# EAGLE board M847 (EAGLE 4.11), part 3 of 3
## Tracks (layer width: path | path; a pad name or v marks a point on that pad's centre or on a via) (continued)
N$122
  Bottom 0.254: E37.6 5.71,92.08 5.71,87.63 18.41,87.63 19.68,88.9 20.95,88.9 22.23,87.63 C4.1
N$123
  Top 0.254: C5.1 20.32,88.27 17.78,90.81 17.78,99.06 E37.14
N$124
  Top 0.254: C5.2 R37.2 20.32,99.06 E37.15
N$125
  Top 0.254: E37.5 5.71,98.43 5.71,104.78 E37.1
N$126  (via drill 0.61)
  Top 0.254: E19.5 128.27,104.14 125.73,106.68 125.73,122.56 124.46,123.83 R38.1 | v152.4,102.87 156.21,106.68 E16.12
  Bottom 0.254: E16.12 E13.1 | v152.4,102.87 132.08,102.87 130.81,104.14 E19.5
N$127  (via drill 0.61)
  Top 0.254: R38.2 C7.1 | v159.38,130.18 159.38,106.05 E16.11
  Bottom 0.254: E16.11 E13.2 | v159.38,130.18 154.94,134.62 C7.1
N$128
  Top 0.254: E16.2 E16.13
N$129
  Top 0.254: E16.3 147.96,104.78 147.96,103.51 E16.5
  Bottom 0.254: E16.5 E16.10
N$130
  Bottom 0.254: E16.6 151.13,99.06 152.4,100.33 162.56,100.33 163.83,101.6 E13.3
N$131
  Bottom 0.254: E16.1 151.13,111.76 154.94,115.57 158.75,115.57 161.93,118.75 254.63,118.75 256.54,116.84 256.54,97.79 257.81,97.79 259.08,96.52 259.08,74.3 252.09,74.3 E2.12
N$132
  Top 0.254: E5.9 233.04,66.68 233.04,67.95 E5.10
  Bottom 0.254: E2.13 250.19,76.2 248.92,74.93 242.57,74.93 241.94,74.3 241.94,73.03 242.57,72.39 245.11,72.39 245.75,71.76 245.75,69.85 236.22,69.85 234.95,68.58 E5.10
N$133  (via drill 0.61)
  Top 0.254: T2.2 v146.05,104.14 146.05,88.27 v145.41,87.63
  Bottom 0.254: E16.4 v146.05,104.14 | v145.41,87.63 181.61,87.63 186.69,82.55 236.85,82.55 238.12,81.28 R39.1
N$134
  Top 0.254: E5.8 231.78,65.41 231.78,74.3 E5.13
N$135  (via drill 0.61)
  Top 0.254: v165.74,60.96 165.74,61.6 E12.10 | v132.08,59.06 132.08,63.5 E18.6
  Bottom 0.254: E18.6 133.35,66.04 132.08,67.31 109.86,67.31 109.86,65.41 E22.8 110.49,63.5 109.22,62.23 49.53,62.23 46.99,64.77 17.78,64.77 16.51,66.04 E36.9 | v165.74,60.96 163.83,59.06 v132.08,59.06
N$136  (via drill 0.61)
  Top 0.254: v184.78,71.12 184.78,99.7 E10.3
  Bottom 0.254: v184.78,71.12 186.06,69.85 231.14,69.85 232.41,71.12 E5.11
N$137  (via drill 0.61)
  Top 0.254: v26.04,62.23 v26.04,71.12
  Bottom 0.254: v26.04,62.23 17.78,62.23 16.51,63.5 E36.8 | v26.04,71.12 E33.11
N$138  (via drill 0.61)
  Top 0.254: v21.59,93.98 21.59,92.08 27.3,86.36 27.3,58.42 32.38,58.42 33.66,59.69 33.66,65.41 E33.10
  Bottom 0.254: v21.59,93.98 E37.11
N$139  (via drill 0.61)
  Top 0.254: 130.18,76.2 132.72,76.2 132.72,73.03 E18.4 | E20.13 130.18,76.2 | v107.31,78.74 107.31,102.24 E23.4 | v163.19,81.28 163.19,80.65 E12.1 | 130.18,76.2 v130.18,81.28
  Bottom 0.254: v107.31,78.74 108.58,77.47 124.46,77.47 125.73,76.2 E20.13 | v130.18,81.28 v163.19,81.28
N$140  (via drill 0.61)
  Top 0.254: E20.11 126.36,71.76 126.36,73.03 E20.12 | v71.12,72.39 71.12,76.2 E27.14
  Bottom 0.254: v71.12,72.39 123.83,72.39 125.09,73.66 E20.12
N$141  (via drill 0.61)
  Top 0.254: v131.44,71.76 131.44,74.93 125.73,74.93 125.09,75.57 125.09,76.84 E20.14
  Bottom 0.254: v131.44,71.76 132.08,72.39 154.94,72.39 156.21,71.12 E15.11
N$142
  Top 0.254: D385.C 114.3,153.67 111.76,156.21 D386.A
N$143
  Top 0.254: E2.5 243.21,69.22 243.21,70.49 E2.4 | 170.18,92.71 170.81,92.71 170.81,97.16 E13.11 | 170.18,92.71 163.83,92.71 161.93,90.81 161.93,70.49 E15.9 | 170.18,92.71 170.18,73.66 E12.11
  Bottom 0.254: E13.11 R53.1 | E2.4 242.57,71.12 241.3,72.39 175.26,72.39 173.99,71.12 E12.11
N$144
  Top 0.254: E22.11 111.12,71.76 111.12,73.03 E22.12 113.67,75.57 113.67,82.55 111.12,85.09 111.12,97.16 E23.6
N$145  (via drill 0.61)
  Top 0.254: v113.67,102.87 114.94,101.6 114.94,78.11 E20.3
  Bottom 0.254: E20.3 120.65,73.66 121.92,74.93 162.56,74.93 163.83,73.66 E12.3 | v113.67,102.87 90.17,102.87 89.53,102.24 88.27,102.24 87.63,101.6 E24.3
N$147
  Bottom 0.254: E15.8 158.75,63.5 160.02,64.77 170.18,64.77 171.45,66.04 E12.9 173.99,66.04 175.26,67.31 223.52,67.31 224.79,68.58 E5.5
N$148  (via drill 0.61)
  Top 0.254: v214.63,64.14 223.52,73.03 223.52,76.2 E5.1
  Bottom 0.254: v214.63,64.14 174.62,64.14 173.99,63.5 E12.8
N$149  (via drill 0.61)
  Top 0.254: v121.92,71.12 121.92,73.66 E20.2
  Bottom 0.254: v121.92,71.12 123.19,69.85 130.81,69.85 133.35,67.31 147.32,67.31 148.59,68.58 E15.5
N$151  (via drill 0.61)
  Top 0.254: v121.92,59.06 121.92,68.58 E20.4
  Bottom 0.254: v121.92,59.06 123.19,57.79 231.78,57.79 241.3,67.31 245.11,67.31 246.38,68.58 246.38,73.03 244.47,73.03 E2.3
N$152  (via drill 0.61)
  Top 0.254: E15.10 161.29,72.39 161.29,97.79 163.83,100.33 170.81,100.33 170.81,102.24 171.45,102.87 180.34,102.87 180.34,99.06 E10.5 | v113.03,96.52 111.76,97.79 111.76,104.14 E23.3
  Bottom 0.254: v113.03,96.52 114.3,95.25 161.29,95.25 163.83,97.79 180.34,97.79 181.61,96.52 E10.5
POWER_OK\  (via drill 0.61)
  Top 0.254: E27.9 67.94,66.68 67.94,67.95 E27.10 | v74.93,118.75 v74.93,68.58 | v146.69,19.05 150.5,22.86 v150.5,45.72
  Bottom 0.254: 146.69,123.19 149.22,120.65 259.08,120.65 261.62,118.11 261.62,71.76 252.09,71.76 E2.11 245.11,64.77 242.57,64.77 232.41,54.61 159.38,54.61 v150.5,45.72 | 146.69,123.19 145.41,124.46 T2.3 | v74.93,118.75 79.38,123.19 146.69,123.19 | v74.93,68.58 E27.10 | v146.69,19.05 143.51,19.05 138.43,13.97 U$2.BV2
PULSE_LA  (via drill 0.61)
  Top 0.254: v19.05,15.24 19.05,47.63 12.7,53.98 12.7,105.41 11.43,106.68 11.43,212.73 95.89,212.73 99.69,208.92 99.69,195.58 T1.1
  Bottom 0.254: v19.05,15.24 17.78,13.97 U$2.DR2
RUN\  (via drill 0.61)
  Top 0.254: E16.9 156.84,98.43 156.84,97.16 E16.8 159.38,94.62 159.38,73.03 v160.02,72.39 | v152.4,17.78 156.21,21.59 156.21,26.67 161.29,31.75 168.28,31.75 168.28,36.2 168.91,36.83 172.72,36.83 172.72,41.91 194.31,63.5 194.31,66.68 195.58,67.95 v195.58,74.93
  Bottom 0.254: v160.02,72.39 173.99,72.39 174.62,73.03 185.42,73.03 187.32,74.93 v195.58,74.93 231.14,74.93 232.41,73.66 E5.12 | v152.4,17.78 145.41,17.78 141.6,13.97 U$2.BU2
SET_GO
  Top 0.254: E18.11 144.15,73.03 144.15,97.16 E19.12
SHIFT_CLOCK
  Top 0.254: E25.8 E24.4
  Bottom 0.254: E6.8 234.95,91.44 233.68,92.71 208.28,92.71 207.01,91.44 E9.8 204.47,91.44 203.2,92.71 81.92,92.71 80.64,91.44 E25.8 77.47,91.44 75.56,89.54 51.44,89.54 49.53,91.44 E31.8
START_ADD\  (via drill 0.61)
  Top 0.254: v231.14,30.48 231.14,68.58 E5.3 | v123.83,29.21 123.83,13.97 U$2.CB1
  Bottom 0.254: 160.02,29.21 v123.83,29.21 63.5,29.21 62.23,30.48 E26.7 | 160.02,29.21 161.29,30.48 E11.7 | 160.02,29.21 210.82,29.21 212.09,30.48 E7.7 217.17,30.48 218.44,29.21 229.87,29.21 v231.14,30.48
STOP\  (via drill 0.61)
  Top 0.254: v108.58,54.61 108.58,65.41 E22.10 | v62.23,49.53 51.44,38.74 v51.44,19.05
  Bottom 0.254: v108.58,54.61 103.5,49.53 v62.23,49.53 | v51.44,19.05 48.9,16.51 17.14,16.51 14.61,13.97 U$2.DS2
SW  (via drill 0.61)
  Top 0.254: v36.2,18.42 50.8,33.02 R32.2
  Bottom 0.254: v36.2,18.42 35.56,17.78 8.89,17.78 5.08,13.97 U$2.DV2
SYSTEM_CLEAR\  (via drill 0.61)
  Top 0.254: E31.9 43.18,88.9 43.18,78.74 E30.13 | v158.12,93.98 154.31,90.17 154.31,81.92 151.13,78.74 E15.1
  Bottom 0.254: E6.9 234.31,93.98 233.04,95.25 208.28,95.25 207.01,93.98 E9.9 204.47,93.98 203.2,95.25 162.56,95.25 161.29,93.98 v158.12,93.98 | 41.27,76.84 41.91,76.2 E30.13 | 41.27,76.84 39.37,78.74 E30.1 | E25.9 77.47,93.98 76.2,95.25 50.8,95.25 49.53,93.98 E31.9 | 41.27,76.84 44.45,80.01 147.32,80.01 148.59,78.74 E15.1
TP4  (via drill 0.61)
  Top 0.254: E20.7 118.75,64.14 118.75,65.41 E20.6 118.75,66.68 118.75,67.95 E20.5 | v32.38,59.69 32.38,64.14 E33.9 | v104.78,15.88 102.23,18.42 v102.23,60.33
  Bottom 0.254: v32.38,59.69 33.02,60.33 v102.23,60.33 103.5,61.6 116.2,61.6 118.11,63.5 E20.7 | v104.78,15.88 104.78,13.97 U$2.CJ2
TS1\  (via drill 0.61)
  Top 0.254: E27.4 60.33,70.49 60.33,69.22 E27.5 62.23,68.58 66.67,64.14 v66.67,54.61 | v95.89,50.8 99.69,46.99 v99.69,15.24
  Bottom 0.254: v66.67,54.61 70.48,50.8 v95.89,50.8 | v99.69,15.24 100.33,14.61 100.97,14.61 101.6,13.97 U$2.CK2
TS3\  (via drill 0.61)
  Top 0.254: E20.10 126.36,67.95 126.36,66.68 E20.9 128.91,64.14 v128.91,18.42
  Bottom 0.254: v128.91,18.42 127.64,17.15 100.33,17.15 97.16,13.97 U$2.CM2
VCC  (via drill 0.61)
  Top 0.635: E7.16 219.71,46.99 C13.1 | E11.16 168.91,46.99 C23.1 | R12.2 R13.2 R14.2 | R15.2 R4.2 R5.2 R6.2 R7.2 | C18.1 250.19,26.04 250.82,26.67 250.82,29.85 E1.8 249.56,32.39 249.56,50.8 C17.1 250.19,51.44 250.82,52.07 250.82,62.87 E2.8 249.56,65.41 249.56,82.55 C16.1 | E4.14 234.95,46.99 C14.1 234.95,51.44 238.76,55.25 R39.2 238.76,71.76 235.59,74.93 235.59,76.84 E5.14 233.04,79.38 233.04,82.55 232.41,83.19 C12.1 | C24.1 171.45,83.19 172.09,82.55 172.09,79.38 E12.14 | C27.1 156.21,83.19 156.84,82.55 156.84,79.38 E15.14 153.67,74.93 C28.1 153.67,46.99 E14.14 | C30.1 140.97,83.19 141.6,82.55 141.6,79.38 E18.14 | C39.1 110.49,83.19 111.12,82.55 111.12,79.38 E22.14 | E20.8 123.19,67.31 123.19,80.65 125.73,83.19 C35.1 125.73,84.46 118.75,91.44 118.75,109.86 E23.14 115.57,113.03 C32.1 | v138.43,26.04 138.43,29.21 E17.8 | R23.2 R22.2 R21.2 R20.2 R3.2 82.55,45.09 80.64,43.18 80.64,36.83 80.01,36.2 R2.2 | C36.1 113.03,46.99 E21.14 116.2,43.82 116.2,28.58 C8.+ 122.56,22.23 v122.56,15.88 | E35.8 13.34,32.39 13.34,50.8 C42.1 | E32.14 29.21,46.99 C46.1 | E29.14 44.45,46.99 C44.1 44.45,51.44 49.53,56.52 49.53,69.85 52.07,72.39 | E26.16 67.94,46.36 67.94,62.87 E27.8 66.67,65.41 66.67,72.39 | 66.67,72.39 66.67,82.55 67.31,83.19 C47.1 67.31,84.46 64.77,87 64.77,87.63 61.59,90.81 61.59,111.76 C48.1 62.23,107.95 E28.14 | C33.1 44.45,83.19 45.09,82.55 45.09,79.38 E30.14 | C38.1 13.97,83.19 14.61,82.55 14.61,79.38 E36.14 | C45.1 29.21,83.19 29.84,82.55 29.84,79.38 E33.14 | 66.67,72.39 52.07,72.39 | 52.07,72.39 C2.+ | D385.A R30.2 114.3,184.79 111.76,187.33 R28.2 | R40.1 R46.1 147.32,192.41 148.59,191.14 148.59,177.8
  Top 0.635: 148.59,177.8 R47.1 147.32,177.17 148.59,175.9 148.59,162.56 | 148.59,177.8 R41.1 | 148.59,162.56 R48.1 147.32,161.93 148.59,160.66 148.59,147.32 | 148.59,162.56 R42.1 | 148.59,147.32 R49.1 | 148.59,147.32 R43.1 149.86,146.69 152.4,144.15 R51.1 | R51.1 R45.1 | R44.1 149.86,132.72 152.4,135.26 R51.1 | E25.14 77.47,107.95 C43.1 | E24.14 92.71,107.95 C40.1 | R37.1 E37.16 14.61,107.32 14.61,110.49 13.97,111.13 C34.1 | E34.14 34.29,107.95 C41.1 | E31.14 46.99,107.95 C37.1 | E3.14 250.19,107.95 C15.1 | E6.14 234.95,107.95 C19.1 | E8.14 219.71,107.95 C20.1 | E10.14 189.23,107.95 C22.1 | E9.14 204.47,107.95 C21.1 | E13.14 171.45,107.95 C25.1 | C26.1 156.21,116.21 156.84,115.57 156.84,112.4 E16.14 | E19.16 135.89,115.57 C31.1 R31.1 142.24,126.37 147.32,131.45 R50.1
  Bottom 0.635: R14.2 R15.2 | R12.2 E11.16 168.91,45.72 167.64,46.99 157.48,46.99 156.21,45.72 E14.14 | R7.2 207.65,45.72 208.91,46.99 218.44,46.99 219.71,45.72 E7.16 222.25,45.72 223.52,44.45 233.68,44.45 234.95,45.72 E4.14 | C18.1 256.54,25.4 C11.+ 259.71,22.23 259.71,13.97 260.35,13.97 U$2.AA2 | C16.1 249.56,82.55 248.28,83.82 C12.1 | 123.83,85.09 125.09,83.82 C35.1 | 123.83,85.09 112.39,85.09 111.12,83.82 C39.1 | 139.06,85.09 140.34,83.82 C30.1 | 139.06,85.09 123.83,85.09 | 154.31,85.09 155.57,83.82 C27.1 | 154.31,85.09 139.06,85.09 | 154.31,85.09 169.54,85.09 170.81,83.82 C24.1 | U$2.BA2 190.5,13.97 189.23,15.24 187.96,15.24 C10.+ 177.8,25.4 137.79,25.4 | 137.79,25.4 135.89,23.5 122.56,23.5 C8.+ | 137.79,25.4 v138.43,26.04 | R2.2 R1.2 | 140.34,52.07 139.06,50.8 C29.1 | 140.34,52.07 151.76,52.07 153.03,50.8 C28.1 | 140.34,52.07 114.94,52.07 113.67,50.8 C36.1 | R23.2 93.34,45.72 94.61,44.45 111.76,44.45 113.03,45.72 E21.14 | v122.56,15.88 125.09,15.88 127,13.97 U$2.CA2 | E32.14 31.75,45.72 33.02,46.99 41.91,46.99 43.18,45.72 E29.14 | C42.1 14.61,50.8 15.88,52.07 27.3,52.07 28.57,50.8 C46.1 | C2.+ 49.53,78.74 E30.14 | E36.14 16.51,78.74 17.78,80.01 27.94,80.01 29.21,78.74 E33.14 31.75,78.74 35.56,82.55 42.55,82.55 43.81,83.82 C33.1 | R50.1 R44.1 | R48.1 D385.A | E25.14 80.01,106.68 81.28,107.95 91.44,107.95 92.71,106.68 E24.14 | R37.1 R36.1 23.5,106.68 24.77,107.95 38.1,107.95 | 38.1,107.95 36.83,106.68 E34.14 | 38.1,107.95 45.72,107.95 46.99,106.68 E31.14 49.53,106.68 50.8,105.41 60.96,105.41 62.23,106.68 E28.14 | C43.1 76.83,111.76 75.56,110.49 64.14,110.49 62.87,111.76 C48.1 | 202.56,113.03 191.13,113.03 189.87,111.76 C22.1
  Bottom 0.635: 202.56,113.03 203.84,111.76 C21.1 | 217.81,113.03 219.07,111.76 C20.1 | 202.56,113.03 217.81,113.03 | 233.04,113.03 234.31,111.76 C19.1 | 217.81,113.03 233.04,113.03 | 233.04,113.03 248.28,113.03 249.56,111.76 C15.1 | E13.14 174.62,106.68 177.16,109.22 R53.2 201.93,109.22 204.47,106.68 E9.14 | C26.1 155.57,116.84 153.03,119.38 R31.1 | C25.1 170.81,111.76 169.54,110.49 160.02,110.49 158.75,111.76 E16.14 | C31.1 135.25,119.38 133.99,118.11 126.36,118.11 125.09,119.38 R34.1 123.83,119.38 121.28,116.84 C32.1 114.94,116.84 113.03,114.94 96.52,114.94 93.34,111.76 C40.1

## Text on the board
Top: 1 | 2 | 3 | 4 | 5 | 6 | 7 | 8 | 9 | 10 | 11 | 12 | 13 | 14 | 15 | 16 | WORD | 17 | 18 | 19 | 20 | 21 | 22 | 23 | 24 | 25 | 26 | 27 | 28 | 29 | 30 | 31 | 32 | 6 | 0 | 7 | 1 | 8 | 2 | 9 | 3 | 10 | 4 | 11 | 5
Bottom: VRS | M847 | MI8E BOOTSTRAP LOADER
